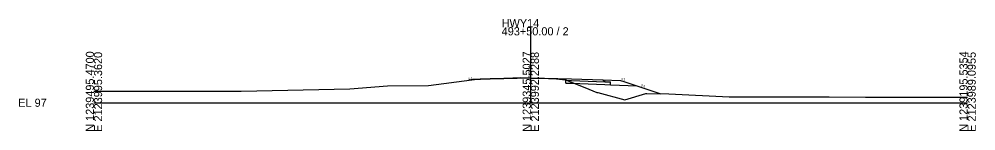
# Model space of a CAD drawing. Extents: x -26 to 303, y -10 to 11521.
# Drawn here: x -25.7 to 302.8, y 4990.3 to 5028.8 of the extents above; entities that cross this region are included whole.
import ezdxf

# ---------------------------------------------------------------- set-up
doc = ezdxf.new("R2010")
doc.units = 0
for name, color, linetype in [('XS_CELL', 7, 'Continuous'), ('XS_P_FINISHED_GRADE', 7, 'Continuous'), ('XS_P_SUBGRADE_GRANULAR', 7, 'Continuous'), ('XS_P_SUBGRADE_LEVELING', 7, 'Continuous'), ('XS_P_SUBGRADE_PAVEMENT', 7, 'Continuous'), ('XS_P_TX_FS_BS', 7, 'Continuous'), ('XS_X_GROUND', 7, 'Continuous'), ('XS_X_GROUND_TX', 7, 'Continuous')]:
    doc.layers.add(name, color=color, linetype=linetype)

msp = doc.modelspace()

# ---------------------------------------------------------------- linework, layer by layer
at = {"layer": 'XS_CELL'}
for p, q in [((150, 5000), (150, 5025.97)), ((0, 5000), (150, 5000)), ((150, 5000), (300, 5000))]:
    msp.add_line(p, q, dxfattribs=at)
at = {"layer": 'XS_P_FINISHED_GRADE'}
for p, q in [((130, 5008.02), (128.8, 5007.72)), ((136, 5008.26), (130, 5008.02)), ((150, 5008.54), (136, 5008.26)), ((150, 5008.54), (164, 5008.26)), ((164, 5008.26), (174.78, 5007.83)), ((174.78, 5007.83), (180.78, 5007.59)), ((180.78, 5007.59), (182, 5007.29)), ((182, 5007.29), (194.64, 5003.08))]:
    msp.add_line(p, q, dxfattribs=at)
at = {"layer": 'XS_P_SUBGRADE_GRANULAR'}
for p, q in [((136, 5008.14), (129.4, 5007.87)), ((162, 5006.72), (162, 5007.72)), ((175.41, 5007.22), (177.41, 5007.14)), ((177.4, 5006.14), (177.4, 5007.16)), ((177.4, 5006.14), (177.4, 5007.16)), ((162, 5006.72), (163.97, 5006.68)), ((163.97, 5006.68), (175.38, 5006.22)), ((175.38, 5006.22), (177.4, 5006.14)), ((177.4, 5006.14), (186.53, 5005.78))]:
    msp.add_line(p, q, dxfattribs=at)
at = {"layer": 'XS_P_SUBGRADE_LEVELING'}
for p, q in [((150, 5008.42), (136, 5008.14)), ((136, 5008.14), (136, 5008.26)), ((150, 5008.42), (162, 5008.18)), ((162, 5008.18), (162, 5008.3))]:
    msp.add_line(p, q, dxfattribs=at)
at = {"layer": 'XS_P_SUBGRADE_PAVEMENT'}
for p, q in [((162, 5007.72), (162, 5008.3)), ((162, 5007.72), (164, 5007.68)), ((164, 5007.68), (175.41, 5007.22)), ((174.78, 5007.83), (175.26, 5007.48)), ((174.78, 5007.83), (175.26, 5007.48)), ((175.26, 5007.48), (175.4, 5007.24)), ((175.26, 5007.48), (175.41, 5007.22))]:
    msp.add_line(p, q, dxfattribs=at)
at = {"layer": 'XS_X_GROUND'}
for p, q in [((114.87, 5005.92), (129.78, 5007.85)), ((129.78, 5007.85), (132.61, 5008.22)), ((132.61, 5008.22), (135.28, 5008.26)), ((135.28, 5008.26), (143.81, 5008.55)), ((143.81, 5008.55), (146.61, 5008.66)), ((146.61, 5008.66), (150, 5008.54)), ((150, 5008.54), (152.07, 5008.47)), ((152.07, 5008.47), (157.44, 5008.32)), ((157.44, 5008.32), (158.81, 5008.19)), ((158.81, 5008.19), (161.97, 5007.92)), ((161.97, 5007.92), (168.57, 5005.25)), ((0, 5003.97), (12.83, 5003.98)), ((12.83, 5003.98), (50.6, 5004.03)), ((50.6, 5004.03), (87.88, 5004.81)), ((87.88, 5004.81), (100.78, 5005.79)), ((100.78, 5005.79), (114.87, 5005.92)), ((168.57, 5005.25), (172.67, 5003.56)), ((172.67, 5003.56), (173.05, 5003.47)), ((173.05, 5003.47), (182.26, 5000.99)), ((182.26, 5000.99), (189.56, 5003.13)), ((189.56, 5003.13), (189.89, 5003.13)), ((189.89, 5003.13), (197.45, 5003.04)), ((197.45, 5003.04), (218.16, 5002.06)), ((218.16, 5002.06), (252.45, 5002)), ((252.45, 5002), (264.98, 5001.94)), ((264.98, 5001.94), (271, 5001.92)), ((271, 5001.92), (300, 5001.91))]:
    msp.add_line(p, q, dxfattribs=at)

# ---------------------------------------------------------------- texts
at = {"layer": 'XS_CELL'}
for s, p in [('HWY14', (140, 5025.97)), ('493+50.00 / 2', (140, 5023.17)), ('EL 97', (-26, 4998.6))]:
    msp.add_text(s, height=2.8, dxfattribs=at).set_placement(p)
for s, p in [('N 1239495.4700', (0, 4990)), ('E 2123995.3620', (2.8, 4990)), ('N 1239345.5027', (150, 4990)), ('E 2123992.2288', (152.8, 4990)), ('N 1239195.5354', (300, 4990)), ('E 2123989.0955', (302.8, 4990))]:
    msp.add_text(s, height=2.8, rotation=90, dxfattribs=at).set_placement(p)
at = {"layer": 'XS_P_TX_FS_BS'}
for s, rotation, p in [('4:1', 14.0362, (128.57, 5007.75)), ('4:1', 345.9638, (180.89, 5007.89)), ('3:1', 341.5651, (187.69, 5005.76))]:
    msp.add_text(s, height=0.8, rotation=rotation, dxfattribs=at).set_placement(p)
at = {"layer": 'XS_X_GROUND_TX'}
msp.add_text('105.54', height=1, rotation=90, dxfattribs=at).set_placement((150, 5008.64))

doc.saveas('drawing.dxf')
